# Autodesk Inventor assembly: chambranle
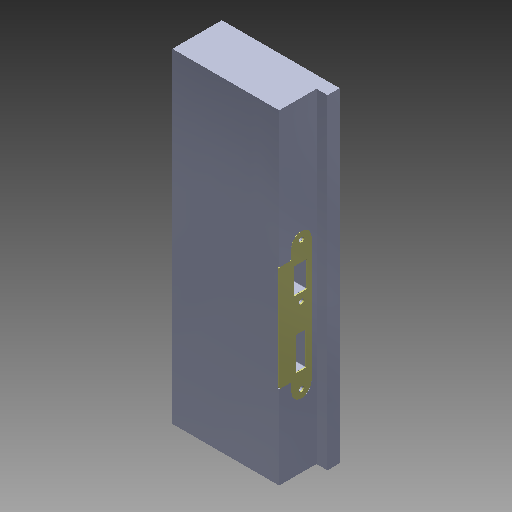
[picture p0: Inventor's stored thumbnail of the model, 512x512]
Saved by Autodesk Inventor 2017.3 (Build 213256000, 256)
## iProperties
Created: 2011-01
Part Number: chambranle
Material: Générique
Document SubType Name: Assembly
Designer: ficho
Author: ficho
Sending System: SolidWorks 2009
Last Author: christophe
Last Saved: 2011-02-10
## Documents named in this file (3)
- G:\travail\année 2019-2020\réforme\toussaint\Serrure biométrique SET\Documentations_pedagogique\Modelisation_Solidworks\chambranle.iam
- G:\travail\année 2019-2020\réforme\toussaint\Serrure biométrique SET\Documentations_pedagogique\Modelisation_Solidworks\gache.ipt
- G:\travail\année 2019-2020\réforme\toussaint\Serrure biométrique SET\Documentations_pedagogique\Modelisation_Solidworks\cadre dormant_.ipt
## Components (2 placed, 2 different names)
1. gache:1
2. cadre dormant_:2
